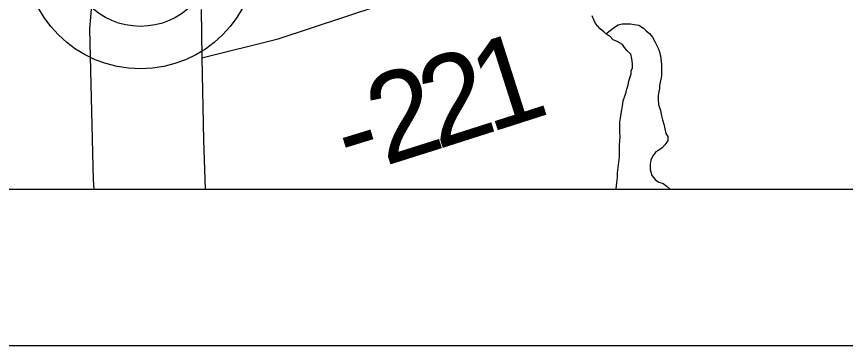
# Model space of a CAD drawing. Extents: x 0 to 34, y 0 to 22.
# Drawn here: x 3.309 to 3.841, y 14 to 14.211 of the extents above; entities that cross this region are included whole.
import ezdxf

# ---------------------------------------------------------------- set-up
doc = ezdxf.new("R2010")
doc.units = 0
for name, color, linetype in [('GM_X_Corporation', 7, 'Continuous'), ('GM_X_Minor_River', 7, 'Continuous'), ('GM_X_State_Route', 7, 'Continuous'), ('GM_X_Township_Road', 7, 'Continuous'), ('GM_X_Township_Road_Text', 7, 'Continuous'), ('GM_X_Unincorporated', 7, 'Continuous'), ('SH_Data', 7, 'Continuous')]:
    doc.layers.add(name, color=color, linetype=linetype)

msp = doc.modelspace()

# ---------------------------------------------------------------- linework, layer by layer
at = {"layer": 'GM_X_Corporation'}
msp.add_lwpolyline([(2.1, 20.38793), (2.1, 14.1), (7.13354, 14.1), (7.12689, 14.40486), (7.12673, 14.41229), (7.12151, 14.6514), (7.11804, 14.81053), (7.10717, 15.38236), (7.08385, 16.60844)], dxfattribs=at)
msp.add_lwpolyline([(2.1, 15.35741), (2.1, 14.1), (7.13354, 14.1), (7.12689, 14.40486), (7.12673, 14.41229), (7.12151, 14.6514), (7.11804, 14.81053), (7.10717, 15.38236), (6.04148, 15.36846), (5.83128, 15.36706), (5.19443, 15.3696), (4.15537, 15.36541), (4.15336, 15.3654), (3.4135, 15.36242), (2.61275, 15.35918)], close=True, dxfattribs=at)
at = {"layer": 'GM_X_Minor_River'}
for points in [[(3.69384, 14.1), (3.6939, 14.10037), (3.69432, 14.10416), (3.69475, 14.10758), (3.69478, 14.11062), (3.6952, 14.11403), (3.69562, 14.11745), (3.69605, 14.12086), (3.69609, 14.12466), (3.69613, 14.12808), (3.69617, 14.13112), (3.69658, 14.13378), (3.69623, 14.13644), (3.69628, 14.14024), (3.69631, 14.1429), (3.69672, 14.14555), (3.69714, 14.14859), (3.69755, 14.15087), (3.69796, 14.15352), (3.69838, 14.15656), (3.69955, 14.15958), (3.70035, 14.16223), (3.70075, 14.16413), (3.70154, 14.16678), (3.70195, 14.16943), (3.70274, 14.17133), (3.70353, 14.17398), (3.70355, 14.17588), (3.70433, 14.17777), (3.70437, 14.18043), (3.70402, 14.18347), (3.7033, 14.18652), (3.70066, 14.18883), (3.69917, 14.19075), (3.69805, 14.19266), (3.69465, 14.1946), (3.69201, 14.19577), (3.68975, 14.19808), (3.68787, 14.19924), (3.68598, 14.20078), (3.68373, 14.20271), (3.68073, 14.20617), (3.67962, 14.20846), (3.67851, 14.21113)], [(3.68739, 14.19963), (3.69286, 14.20374), (3.69516, 14.20524), (3.69783, 14.20597), (3.70087, 14.20593), (3.70315, 14.2059), (3.70543, 14.2055), (3.70846, 14.20508), (3.71148, 14.20314), (3.71336, 14.20122), (3.71524, 14.19968), (3.71711, 14.19738), (3.71898, 14.19431), (3.72083, 14.19049), (3.72157, 14.18858), (3.72229, 14.18553), (3.72265, 14.18363), (3.72298, 14.17983), (3.72296, 14.17755), (3.72293, 14.17489), (3.7229, 14.17261), (3.72168, 14.16654), (3.72166, 14.16464), (3.72126, 14.16274), (3.72085, 14.16009), (3.72081, 14.15743), (3.72116, 14.15439), (3.72225, 14.15057), (3.72297, 14.14714), (3.7237, 14.14448), (3.72443, 14.14181), (3.72515, 14.13876), (3.72587, 14.13571), (3.72699, 14.1338), (3.72696, 14.13114), (3.72503, 14.1285), (3.72348, 14.12662), (3.72119, 14.12512), (3.71927, 14.12401), (3.71734, 14.12137), (3.71617, 14.11872), (3.71575, 14.11607), (3.71571, 14.11265), (3.71681, 14.10883), (3.71906, 14.10615), (3.72132, 14.1046), (3.72397, 14.10381), (3.72661, 14.10188), (3.72844, 14.1)]]:
    msp.add_lwpolyline(points, dxfattribs=at)
at = {"layer": 'GM_X_State_Route'}
msp.add_lwpolyline([(3.42783, 14.21526), (3.42827, 14.18412), (3.42936, 14.13148), (3.43032, 14.1)], dxfattribs=at)
at = {"layer": 'GM_X_Township_Road'}
for points in [[(3.35913, 14.1), (3.35868, 14.10592), (3.35634, 14.20247), (3.35778, 14.21808), (3.36024, 14.23863), (3.36832, 14.28001)], [(3.42827, 14.18412), (3.47712, 14.19644), (3.71414, 14.27465)]]:
    msp.add_lwpolyline(points, dxfattribs=at)
at = {"layer": 'GM_X_Unincorporated'}
for radius in [0.0744, 0.04716]:
    msp.add_circle((3.38888, 14.25153), radius, dxfattribs=at)
at = {"layer": 'SH_Data'}
for p, q in [((2.1, 14.1), (8.9, 14.1)), ((2, 14), (9, 14))]:
    msp.add_line(p, q, dxfattribs=at)

# ---------------------------------------------------------------- texts
at = {"layer": 'GM_X_Township_Road_Text'}
for s, rotation, p in [('1', 17.7447, (3.61247, 14.13604)), ('2', 17.6962, (3.57908, 14.12538)), ('2', 17.5107, (3.54551, 14.11479)), ('-', 17.0886, (3.52277, 14.1078))]:
    msp.add_text(s, height=0.05682, rotation=rotation, dxfattribs=at).set_placement(p)

doc.saveas('drawing.dxf')
